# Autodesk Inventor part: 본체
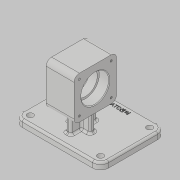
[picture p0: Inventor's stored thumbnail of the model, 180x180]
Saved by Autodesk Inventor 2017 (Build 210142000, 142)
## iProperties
Part Number: 본체
Material: 일반
Document SubType Name: Modeling
Designer: mrc
Density: 1 g/cm^3
Appearance: 기본값
Author: mrc
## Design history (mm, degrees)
sketch "스케치1"
  geometry: L1 (65, -49)-(-65, -49); L2 (-65, -49)-(-65, 49); L3 (-65, 49)-(65, 49); L4 (65, 49)-(65, -49); L5 (65, -49)-(-65, 49); L6 (-65, -49)-(65, 49); 1 further point
  constraints: 12 end point, 2 midpoint, 2 parallel, 1 horizontal, 1 perpendicular
  dimensions: "d1" = 130 distance of L2.end L3.end; "d2" = 98 distance of L1.end L2.end
extrude "돌출1" new body sketch "스케치1" distance "d3" = 10; taper "d4" = 0 deg
sketch "스케치7"
  geometry: L1 (0, -49)-(0, 49) reference; L2 (0, -49)-(10, -49) reference; L3 (10, 49)-(10, -49) reference; L4 (0, 49)-(10, 49) reference; L5 (0, -49)-(0, 13); L6 (0, 13)-(70, 13); L7 (38, -19)-(102, -19); L8 (102, -19)-(102, 45); L9 (102, 45)-(38, 45); L10 (38, 45)-(38, -19); L11 (38, -19)-(102, 45); L12 (102, -19)-(38, 45); 1 further point
  constraints: 16 end point, 2 midpoint, 2 parallel, 2 perpendicular, 1 horizontal, 1 point on line
  dimensions: "d21" = 62 distance of L1.start L5.end; "d22" = 70 distance of L5.end L6.end; "d23" = 64 distance of L9.end L8.end; "d24" = 64 distance of L8.end L7.end
extrude "돌출3" join sketch "스케치7" stored distance "d25" = 42; taper "d26" = 0 deg
sketch "스케치8"
  geometry: L1 (49, 10)-(49, 0) reference; L2 (49, 0)-(-49, 0) reference; L3 (-49, 0)-(-49, 10) reference; L4 (-49, 10)-(49, 10) reference; L5 (19, 38)-(-45, 38) reference; L6 (-45, 38)-(-45, 102) reference; L7 (-45, 102)-(19, 102) reference; L8 (19, 102)-(19, 38) reference; L9 (19, 38)-(19, 102) reference; L10 (19, 102)-(-45, 102) reference; L11 (-45, 102)-(-45, 38) reference; L12 (-45, 38)-(19, 38) reference; C1 r 20.523 at (-13, 70); 1 further point
  constraints: 1 centre point
hole "구멍2" sketch "스케치8" at (-13, 70) diameter "d27" = 36; stored, may be unused: countersink angle "d31" = 90 deg, drill point angle "d33" = 118 deg; dims "d28" = 6, "d29" = 42, "d30" = 15, "d32" = 8
sketch "스케치9"
  geometry: L1 (19, 38)-(19, 102) reference; L2 (19, 102)-(-45, 102) reference; L3 (-45, 102)-(-45, 38) reference; L4 (-45, 38)-(19, 38) reference; L5 (-13, 70)-(-13, 94); L6 (-13, 94)-(-37, 94); C1 r 21 at (-13, 70) reference; C2 r 4.148 at (-37, 94); 1 further point
  constraints: 4 end point, 1 centre point, 1 coincident, 1 perpendicular, 1 vertical
  dimensions: "d34" = 24 distance of L5.start L5.end; "d35" = 24 distance of L5.end L6.end
hole "구멍3" sketch "스케치9" at (-37, 94) diameter "d36" = 3.242; stored, may be unused: countersink angle "d40" = 90 deg, drill point angle "d42" = 118 deg; dims "d37" = 8, "d38" = 42, "d39" = 15, "d41" = 10
fillet "모깎기1" dims "d55" = 8
sketch "스케치11"
  geometry: L1 (4, -33)-(-4, -33); L2 (-4, -33)-(-4, 7); L3 (-4, 7)-(4, 7); L4 (4, 7)-(4, -33); L5 (4, -33)-(-4, 7); L6 (-4, -33)-(4, 7); L7 (17, -17)-(-17, -17); L8 (-17, -17)-(-17, -9); L9 (-17, -9)-(17, -9); L10 (17, -9)-(17, -17); L11 (17, -17)-(-17, -9); L12 (-17, -17)-(17, -9); L13 (65, 49)-(65, -49) reference; L14 (-65, 49)-(65, 49) reference; 3 further points
  constraints: 24 end point, 5 midpoint, 4 parallel, 2 horizontal, 2 perpendicular
  dimensions: "d73" = 34 distance of L8.end L9.end; "d74" = 40 distance of L3.end L1.start; "d75" = 65 distance from line of L13 point (0, -13); "d76" = 62 distance from line of point (0, -13) L14; "d77" = 8 distance of L2.end L3.end; "d78" = 8 distance of L7.end L8.end
extrude "돌출4" join sketch "스케치11" stored distance "d79" = 42; taper "d80" = 0 deg
sketch "스케치12"
  geometry: L1 (-17, -17)-(-17, -9) reference; L2 (-17, -9)-(-4, -9) reference; L3 (-4, -9)-(-4, 7) reference; L4 (-4, 7)-(4, 7) reference; L5 (4, 7)-(4, -9) reference; L6 (4, -9)-(17, -9) reference; L7 (17, -9)-(17, -17) reference; L8 (17, -17)-(4, -17) reference; L9 (4, -17)-(4, -33) reference; L10 (4, -33)-(-4, -33) reference; L11 (-4, -33)-(-4, -17) reference; L12 (-4, -17)-(-17, -17) reference; L13 (65, 49)-(-65, 49) reference; L14 (-65, 49)-(-65, -49) reference; L15 (-65, -49)-(65, -49) reference; L16 (65, -49)-(65, 49) reference; L17 (-65, 49)-(-53, 49); L18 (-53, 49)-(-53, 37); C1 r 7.324 at (-53, 37); 1 further point
  constraints: 4 end point, 1 centre point, 1 coincident, 1 perpendicular, 1 point on line
  dimensions: "d81" = 12 distance of L13.end L17.end; "d82" = 12 distance of L17.end L18.end
hole "구멍4" sketch "스케치12" at (-53, 37) diameter "d83" = 9; stored, may be unused: countersink angle "d87" = 90 deg, drill point angle "d89" = 118 deg; dims "d84" = 8, "d85" = 42, "d86" = 15, "d88" = 10
fillet "모깎기2" dims "d96" = 12
chamfer "모따기1" distance "d97" = 1; stored, may be unused: second distance "d98" = 2, angle "d99" = 45 deg
fillet "모깎기3" dims "d100" = 3
sketch "스케치14"
  geometry: L1 (-53, 49)-(53, 49) reference; L2 (65, 37)-(65, -37) reference; L3 (53, -49)-(-53, -49) reference; L4 (-65, -37)-(-65, 37) reference; L5 (0, 49)-(0, 39); C1 r 4.5 at (53, -37) reference; C2 r 4.5 at (-53, -37) reference; C3 r 4.5 at (53, 37) reference; C4 r 4.5 at (-53, 37) reference; A1 r 12 centre (-53, 37) between (-53, 49) and (-65, 37) reference; A2 r 12 centre (53, 37) between (65, 37) and (53, 49) reference; A3 r 12 centre (53, -37) between (53, -49) and (65, -37) reference; A4 r 12 centre (-53, -37) between (-65, -37) and (-53, -49) reference; 2 further points
  constraints: 2 end point, 1 coincident, 1 midpoint, 1 vertical, 1 other
  dimensions: "d103" = 10 distance of L5.start L5.end
  node "투영된 루프8"
fillet "모깎기5" dims "d104" = 3
feature "엠보싱1" dims "d52" = 20, "d73" = 34, "d105" = 0.5, "d106" = 0
node "솔리드1"
pattern_linear "직사각형 패턴1" dims "d45" = 48, "d48" = 48
mirror "미러2"
mirror "미러3"
pattern_linear "직사각형 패턴2" dims "d51" = 48, "d54" = 48
pattern_linear "직사각형 패턴3" dims "d92" = 106, "d95" = 74
node "투영된 루프2"
node "투영된 루프3"
node "투영된 루프4"
node "투영된 루프6"
node "절단 모서리 투영1"
